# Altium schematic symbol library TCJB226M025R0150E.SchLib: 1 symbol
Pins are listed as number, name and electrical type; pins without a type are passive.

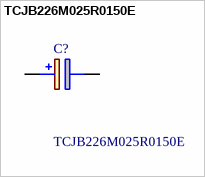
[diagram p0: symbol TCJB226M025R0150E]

## TCJB226M025R0150E
designator C?
Capacitor Polymer 25V 22uF 20% 1210; Manufacturer_Name: Kyocera AVX; Geometry.Height: 2.1mm
footprint CAPPM3528X210N
pins: 1 +, 2 -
